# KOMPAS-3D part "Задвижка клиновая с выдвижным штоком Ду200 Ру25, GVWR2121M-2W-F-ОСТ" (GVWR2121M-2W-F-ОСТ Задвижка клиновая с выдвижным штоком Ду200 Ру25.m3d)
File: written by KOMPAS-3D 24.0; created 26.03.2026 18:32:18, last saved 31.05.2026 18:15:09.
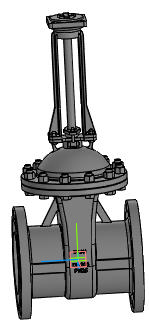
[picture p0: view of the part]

Document properties: Автор: R2D2; Полное имя файла: E:\Работа\Зайцев\GVWR2121M-2W-F-ОСТ Задвижка клиновая 30с964нж DN.ru Ду50-300 Ру25\исходные материалы\DN200\DN200\GVWR2121M-2W-F-ОСТ Задвижка клиновая с выдвижным штоком Ду200 Ру25.m3d

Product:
- Part/product: Задвижка клиновая с выдвижным штоком Ду200 Ру25  | designation GVWR2121M-2W-F-ОСТ
    Масса: 130
    Раздел спецификации: Прочие изделия
    Примечание: D040-09832

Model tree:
1. Операция без истории:1

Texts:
  GVWR2121M-2W-F-ОСТ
